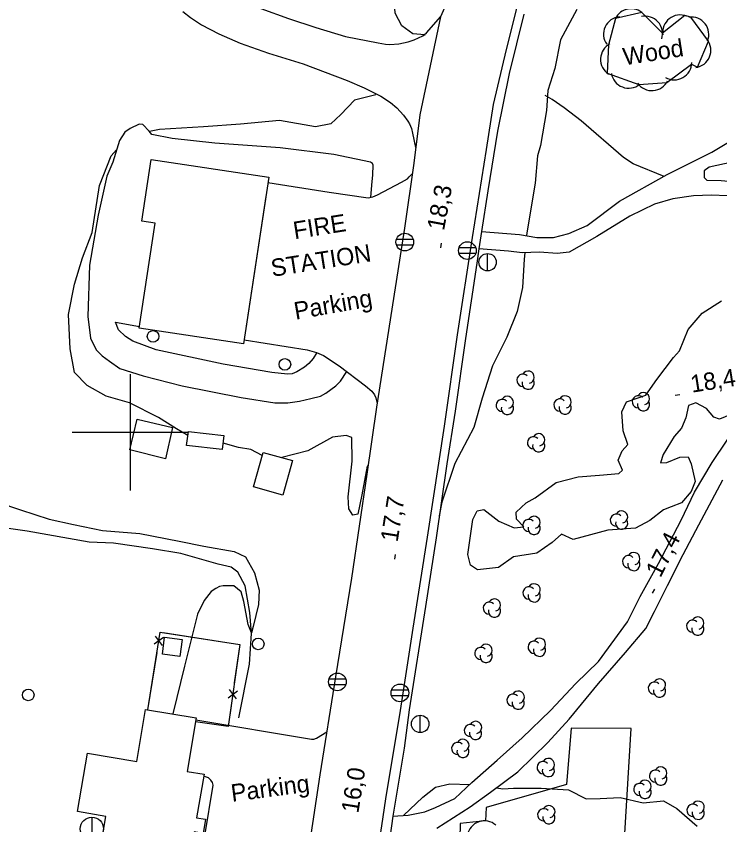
# Model space of a CAD drawing. Extents: x 646142 to 649934, y 5874075 to 5876351.
# Drawn here: x 646580.4 to 646701.5, y 5874932.5 to 5875071.6 of the extents above; entities that cross this region are included whole.
import ezdxf

# ---------------------------------------------------------------- set-up
doc = ezdxf.new("R2010")
doc.units = 0
for name, color, linetype in [('Niveau 19', 7, 'Continuous'), ('Niveau 2', 7, 'Continuous'), ('Niveau 21', 7, 'Continuous'), ('Niveau 22', 7, 'Continuous'), ('Niveau 3', 7, 'Continuous'), ('Niveau 31', 7, 'Continuous'), ('Niveau 34', 7, 'Continuous'), ('Niveau 36', 7, 'Continuous'), ('Niveau 37', 7, 'Continuous'), ('Niveau 4', 7, 'Continuous'), ('Niveau 41', 7, 'Continuous'), ('Niveau 44', 7, 'Continuous'), ('Niveau 52', 7, 'Continuous'), ('Niveau 61', 7, 'Continuous')]:
    doc.layers.add(name, color=color, linetype=linetype)

msp = doc.modelspace()

# ---------------------------------------------------------------- linework, layer by layer
at = {"layer": 'Niveau 19'}
for points in [[(646641.42, 5875040.42), (646641.63, 5875042.53), (646641.77, 5875044.33), (646641.84, 5875045.99), (646641.71, 5875046.26), (646641.4, 5875046.47), (646635.06, 5875047.78), (646625.83, 5875048.97), (646614.56, 5875049.76), (646607.26, 5875050.58), (646603.75, 5875051.27), (646603.26, 5875051.8), (646602.16, 5875052.99), (646601.58, 5875053.02), (646599.98, 5875052.3), (646599.09, 5875051.62), (646598.17, 5875050.21), (646597.92, 5875049.46), (646597.04, 5875046.51), (646595.97, 5875044.1), (646594.51, 5875037.36), (646593.01, 5875028.77), (646592.7, 5875019.93), (646593.19, 5875016.2), (646594.13, 5875014.22), (646595.16, 5875013.17), (646596.43, 5875012.24), (646598.21, 5875010.97), (646602.26, 5875009.71), (646608.94, 5875008), (646619.13, 5875005.99), (646624.89, 5875005.1), (646627.16, 5875005.1), (646629.17, 5875005.36), (646631.11, 5875005.81), (646632.8, 5875006.24), (646633.72, 5875006.72), (646635.43, 5875007.97), (646636.21, 5875008.82), (646637.29, 5875010.45)], [(646632.16, 5875013.71), (646631.49, 5875012.72), (646630.77, 5875011.82), (646630.01, 5875011.21), (646628.69, 5875010.39), (646627.9, 5875010.06), (646627.08, 5875010.02), (646624.39, 5875010.32), (646616.01, 5875011.7), (646604.51, 5875014.2), (646600.48, 5875015.66), (646599.18, 5875016.49), (646597.99, 5875017.62), (646597.51, 5875018.93), (646601.63, 5875018.21)]]:
    msp.add_lwpolyline(points, dxfattribs=at)
at = {"layer": 'Niveau 2'}
for points in [[(646650.73, 5875068.29), (646650.71, 5875068.4), (646648.66, 5875068.54), (646646.8, 5875069.97), (646645.63, 5875072.15), (646645.5, 5875073.77), (646647.46, 5875079.63), (646647.81, 5875081.69), (646646.81, 5875083.25), (646644.56, 5875085.18), (646640.6, 5875087.32), (646634.24, 5875090.51), (646629.79, 5875092.33), (646626.03, 5875093.44), (646624.21, 5875094.41), (646623.63, 5875095.77), (646623.67, 5875097.46), (646626.36, 5875102.85), (646628.98, 5875108.46), (646631.23, 5875113.58), (646634.8, 5875119.82)], [(646676.93, 5875072.77), (646674.11, 5875067.54), (646673.12, 5875062.58), (646671.92, 5875058.82), (646671.69, 5875055.36), (646670.67, 5875049.35), (646670.12, 5875047.56), (646669.76, 5875042.87), (646668.31, 5875034.32), (646668.26, 5875033.82)], [(646642.28, 5875058.07), (646638.62, 5875057.17), (646636.27, 5875054.66), (646634.54, 5875053.07), (646631.91, 5875052.58), (646625.72, 5875053.63), (646619.02, 5875053), (646612.61, 5875052.57), (646605.03, 5875052.11), (646603.31, 5875051.74)], [(646609.95, 5874999.46), (646608, 5875000.59), (646604.87, 5875002.57), (646599.89, 5875005.1), (646595.9, 5875006.2), (646592.61, 5875008.03), (646590.44, 5875010.31), (646589.65, 5875014.34), (646589.39, 5875020.26), (646590.42, 5875025.47), (646591.79, 5875030), (646593.46, 5875034.39), (646594.71, 5875042.47), (646596.73, 5875047.58), (646597.67, 5875048.62)], [(646667.94, 5875030.89), (646667.82, 5875029.79), (646667.58, 5875024.94), (646666.64, 5875020.79), (646664.86, 5875016.35), (646662.36, 5875011.44), (646660.61, 5875005.89), (646659.17, 5875000.83), (646655.9, 5874994.63), (646653.66, 5874988), (646653.22, 5874985.61)], [(646688.81, 5875006.41), (646690.68, 5875009.06), (646693.56, 5875012.89), (646694.57, 5875014.01), (646696.06, 5875017.68), (646698.5, 5875020.48), (646701.81, 5875022.6)], [(646691.83, 5874986.67), (646689.49, 5874984.8), (646686.98, 5874983.5), (646682.25, 5874983.14), (646676.28, 5874981.57), (646674.24, 5874982.46), (646672.67, 5874981.06), (646670.03, 5874979.23), (646666.02, 5874978.57), (646663.44, 5874976.74), (646659.81, 5874976.35), (646658.59, 5874977.12), (646658.14, 5874978.95), (646658.98, 5874985.02), (646659.73, 5874986.47), (646660.87, 5874986.74), (646663.48, 5874984.72), (646666.13, 5874983.59), (646667.8, 5874983.72), (646666.53, 5874985.07), (646666.49, 5874986.24), (646668.21, 5874987.88), (646669.71, 5874988.75), (646673.33, 5874991.36), (646677.14, 5874992.35), (646680.83, 5874992.64), (646684.12, 5874992.89), (646684.77, 5874993.46), (646684.04, 5874995.21), (646684.72, 5874996.84), (646685.68, 5874997.9), (646684.91, 5875000.23), (646684.63, 5875003.53), (646685.48, 5875005.22), (646688.81, 5875006.41)], [(646704.1, 5875003.33), (646701.46, 5875002.25), (646700.5, 5875002.59), (646699.22, 5875004.12), (646697.39, 5875005.09), (646696.15, 5875004.64), (646695.69, 5875002.51), (646694.91, 5875000.7), (646693.64, 5874999.27), (646691.8, 5874996.21), (646691.34, 5874994.72), (646692.38, 5874994.8), (646694.63, 5874995.73), (646696.07, 5874995.79), (646696.58, 5874994.6), (646697.3, 5874991.51), (646696.62, 5874989.83), (646694.93, 5874987.84), (646693.13, 5874987.18), (646691.83, 5874986.67)], [(646640.99, 5874994.22), (646640.83, 5874994.18), (646639.9, 5874989.27), (646639.19, 5874985.9), (646638.33, 5874985.77), (646637.66, 5874986.83), (646637.55, 5874988.92), (646638.21, 5874995.02), (646638.16, 5874999.1), (646637.2, 5874999.43), (646634.84, 5874999.19), (646630.62, 5874996.83), (646626.1, 5874995.65)], [(646622.76, 5874996.02), (646620.77, 5874997.07), (646618.65, 5874997.37), (646615.99, 5874998.12)], [(646577.18, 5874987.99), (646581.1, 5874986.64), (646586.08, 5874985.03), (646590.23, 5874984.12), (646595.27, 5874983.11), (646601.66, 5874982.61), (646608.47, 5874981.26), (646612.67, 5874980.42), (646617.94, 5874979.48), (646619.87, 5874978.58), (646621.44, 5874975.84), (646622.21, 5874972.81), (646622.13, 5874970.35), (646621.21, 5874966.6), (646620.91, 5874965.47), (646620.3, 5874966.91), (646619.57, 5874970.88), (646619.1, 5874972.58)], [(646619.1, 5874972.58), (646619.1, 5874972.58), (646617.88, 5874973.6), (646617.88, 5874973.6), (646616.01, 5874973.61), (646615.37, 5874973.45), (646614.73, 5874973.12), (646613.97, 5874972.61), (646612.74, 5874971.04), (646611.58, 5874968.73), (646609.35, 5874959.78), (646607.34, 5874951.54)], [(646647.04, 5874934.07), (646650.41, 5874937.24), (646652.6, 5874938.92), (646655.06, 5874939.52), (646658.44, 5874939.39)], [(646663.06, 5874938.82), (646664.15, 5874938.65), (646666, 5874938.79), (646670.77, 5874938.75), (646675.45, 5874938.47), (646678.54, 5874936.96), (646680.93, 5874936.97), (646684.34, 5874937.18), (646688.31, 5874936.26), (646691.83, 5874936.59), (646694.15, 5874935.25), (646697.6, 5874932.25)]]:
    msp.add_lwpolyline(points, dxfattribs=at)
at = {"layer": 'Niveau 21'}
for points in [[(646660.51, 5875034.56), (646667.06, 5875034.01), (646670, 5875033.53), (646672.91, 5875033.52), (646675.53, 5875034.19), (646678.66, 5875035.59), (646684.25, 5875039.75), (646692.46, 5875044.34), (646700.16, 5875048.18), (646707.02, 5875052.32), (646714.63, 5875058.49), (646722.48, 5875064.67), (646731.56, 5875071.3), (646740.22, 5875077.43)], [(646666.76, 5875073.84), (646664.76, 5875065.88), (646662.53, 5875056.4), (646661.28, 5875048.67), (646658.88, 5875033.5), (646656.32, 5875016.76), (646654.08, 5875001.03), (646651.13, 5874981.97), (646648.69, 5874966.3), (646646.48, 5874952.16), (646643.99, 5874936.91), (646640, 5874910.28), (646637.43, 5874893.45), (646634.9, 5874876.22), (646631.36, 5874853.87), (646630.32, 5874846.31)], [(646654.14, 5875073.04), (646653.43, 5875071.52), (646649.87, 5875054.63), (646648.82, 5875046.29), (646647.21, 5875035.13), (646642.42, 5875004.35), (646640.75, 5874992.79), (646638.11, 5874974.93), (646635.37, 5874957.92), (646632.67, 5874941.05), (646628.69, 5874914.81), (646625.11, 5874891.13), (646620.83, 5874863.45), (646619.85, 5874857.12), (646619.38, 5874853.76), (646619.06, 5874851.3)], [(646740.49, 5875073.2), (646731.08, 5875066.31), (646725.72, 5875062.41), (646716.46, 5875055.07), (646708.41, 5875048.52), (646705.75, 5875046.92), (646699.71, 5875045.64), (646698.83, 5875044.99), (646698.81, 5875043.83), (646699.31, 5875043.4), (646701.75, 5875043.35), (646704.21, 5875043.08)], [(646702.8, 5875040.67), (646700.12, 5875040.81), (646696.99, 5875040.69), (646693.44, 5875040.19), (646690.26, 5875039.25), (646686.02, 5875037.18), (646680.38, 5875033.72), (646675.61, 5875031.02), (646673.54, 5875030.75), (646670.5, 5875030.98), (646667.49, 5875030.87), (646665.14, 5875031.16), (646660.06, 5875031.58)], [(646645.23, 5874933.93), (646647.89, 5874934.14), (646650.75, 5874934.71), (646652.55, 5874935.43), (646655.92, 5874936.98), (646658.83, 5874939.77), (646663.17, 5874943.6), (646667.51, 5874947.44), (646672.35, 5874952.13), (646676.74, 5874956.78), (646680.61, 5874960.58), (646685.63, 5874967.37), (646687.82, 5874971.74), (646690.95, 5874977.45), (646694.87, 5874984.86), (646697.14, 5874989.7), (646700.2, 5874994.82), (646705.27, 5875002.31)], [(646652.79, 5874931.87), (646658.54, 5874935.58), (646662.06, 5874938.07), (646666.77, 5874941.58), (646671.94, 5874946.65), (646675.56, 5874950.66), (646680.63, 5874956.76), (646685.31, 5874962.14), (646688.8, 5874966.25), (646690.3, 5874969.16), (646692.49, 5874973.64), (646695.19, 5874978.98), (646697.9, 5874984.08), (646702.02, 5874991.85)]]:
    msp.add_lwpolyline(points, dxfattribs=at)
at = {"layer": 'Niveau 22'}
for points in [[(646667.76, 5875071.97), (646665.24, 5875061.76), (646663.27, 5875051.83), (646661.56, 5875041.57), (646660.51, 5875034.56), (646660.06, 5875031.58), (646659.69, 5875029.08), (646657.74, 5875016.12), (646655.98, 5875003.64), (646654.52, 5874994.56), (646652.67, 5874981.84), (646650.85, 5874970.05), (646648.02, 5874952.23), (646647.17, 5874945.63), (646645.23, 5874933.93), (646644.74, 5874930.25), (646644.01, 5874924.74), (646642.84, 5874916.36), (646640.89, 5874904.65), (646639.63, 5874895.9), (646637.92, 5874885.6), (646635.53, 5874870.69), (646633.22, 5874854.95), (646632.26, 5874848.21)], [(646691.93, 5875044.04), (646686.61, 5875046.18), (646684.95, 5875047.26), (646677.68, 5875053.61), (646674.72, 5875055.86), (646672.64, 5875057.24), (646671.45, 5875057.93)]]:
    msp.add_lwpolyline(points, dxfattribs=at)
at = {"layer": 'Niveau 3'}
for p, q in [((646653.47, 5875031.77), (646653.61, 5875032.55)), ((646693.86, 5875006.4), (646694.65, 5875006.52)), ((646645.56, 5874978.18), (646645.69, 5874978.97)), ((646689.94, 5874972.31), (646690.31, 5874973.02))]:
    msp.add_line(p, q, dxfattribs=at)
at = {"layer": 'Niveau 31'}
for points in [[(646623.35, 5875040.56), (646619.51, 5875015.21), (646601.58, 5875017.9), (646604.3, 5875036.01), (646602.02, 5875036.35), (646603.61, 5875046.93), (646623.86, 5875043.89), (646619.51, 5875015.21)], [(646606.1, 5874995.46), (646599.94, 5874996.96), (646601.24, 5875002.28), (646607.31, 5875000.8), (646606.1, 5874995.46)], [(646610.04, 5875000.12), (646616.13, 5874999.48), (646615.87, 5874997.07), (646609.72, 5874997.71), (646610.04, 5875000.12)], [(646627.93, 5874995.14), (646626.29, 5874989.21), (646621.26, 5874990.6), (646622.9, 5874996.53), (646627.93, 5874995.14)], [(646605.55, 5874961.8), (646605.93, 5874964.75), (646608.96, 5874964.35), (646608.58, 5874961.4), (646605.55, 5874961.8)], [(646594.67, 5874927.11), (646595.82, 5874933.92), (646590.95, 5874934.74), (646592.64, 5874944.78), (646601.16, 5874943.34), (646602.67, 5874952.33), (646611.36, 5874950.86), (646609.81, 5874941.65), (646612.72, 5874941.16), (646611.45, 5874933.67), (646613, 5874933.41), (646612.59, 5874930.99), (646611.02, 5874931.25), (646610.5, 5874928.19), (646608.3, 5874928.56), (646607.69, 5874924.92), (646594.67, 5874927.11)]]:
    msp.add_lwpolyline(points, dxfattribs=at)
at = {"layer": 'Niveau 34'}
msp.add_line((646593.41, 5874933.77), (646593.41, 5874929.77), dxfattribs=at)
msp.add_circle((646593.42, 5874931.78), 2, dxfattribs=at)
at = {"layer": 'Niveau 36'}
for p, q in [((646648.73, 5875033.19), (646645.85, 5875033.19)), ((646645.85, 5875032.27), (646648.73, 5875032.27)), ((646659.5, 5875031.72), (646656.62, 5875031.72)), ((646656.62, 5875030.8), (646659.5, 5875030.8)), ((646661.54, 5875027.76), (646661.54, 5875030.76)), ((646637.11, 5874957.52), (646634.23, 5874957.52)), ((646634.23, 5874956.6), (646637.11, 5874956.6)), ((646647.89, 5874955.61), (646645.01, 5874955.61)), ((646645.01, 5874954.69), (646647.89, 5874954.69)), ((646649.95, 5874948.31), (646649.95, 5874951.31))]:
    msp.add_line(p, q, dxfattribs=at)
for centre, radius in [((646647.29, 5875032.73), 1.52), ((646658.06, 5875031.27), 1.52), ((646661.54, 5875029.27), 1.5), ((646603.95, 5875016.51), 1), ((646626.64, 5875011.69), 1), ((646622.06, 5874963.58), 1), ((646635.68, 5874957.06), 1.52), ((646582.47, 5874954.81), 1), ((646646.45, 5874955.16), 1.52), ((646649.94, 5874949.82), 1.5)]:
    msp.add_circle(centre, radius, dxfattribs=at)
at = {"layer": 'Niveau 37'}
for points in [[(646603.04, 5874952.26), (646605.2, 5874965.6), (646618.86, 5874963.5), (646616.89, 5874949.37), (646611.24, 5874950.16)], [(646603.04, 5874952.26), (646605.2, 5874965.6), (646618.86, 5874963.5), (646616.89, 5874949.37), (646611.24, 5874950.16)], [(646603.04, 5874952.26), (646605.2, 5874965.6), (646618.86, 5874963.5), (646616.89, 5874949.37), (646611.24, 5874950.16)], [(646605.68, 5874965.53), (646615.57, 5874964.01)], [(646605.77, 5874964.69), (646604.15, 5874963.52)], [(646605.55, 5874963.3), (646604.37, 5874964.92)], [(646615.57, 5874964.01), (646618.86, 5874963.5), (646617.94, 5874956.9)], [(646603.04, 5874952.26), (646604.64, 5874962.13)], [(646616.87, 5874954.32), (646618.47, 5874955.53)], [(646617.06, 5874955.72), (646618.27, 5874954.12)], [(646617.39, 5874952.94), (646616.89, 5874949.37), (646611.24, 5874950.16)]]:
    msp.add_lwpolyline(points, dxfattribs=at)
at = {"layer": 'Niveau 4'}
msp.add_lwpolyline([(646618.74, 5874950.86), (646620.54, 5874960.1), (646620.92, 5874965.39), (646620.62, 5874968.98), (646619.78, 5874973.59), (646618.54, 5874975.94), (646617.42, 5874976.79), (646615.16, 5874977.32), (646608.72, 5874979.16), (646603.87, 5874979.95), (646597.14, 5874980.95), (646592.94, 5874981.1), (646582.29, 5874982.97), (646578.63, 5874983.5)], dxfattribs=at)
at = {"layer": 'Niveau 41'}
msp.add_lwpolyline([(646648.82, 5874922.16), (646647.61, 5874909.9), (646651.04, 5874909.58), (646650.78, 5874904.8), (646670.34, 5874899.89), (646671.57, 5874903.81), (646680.73, 5874901.67), (646681.68, 5874905.56), (646699.43, 5874902.98), (646700.86, 5874914.1), (646690.39, 5874915.8), (646689.63, 5874930.96), (646685.17, 5874930.97), (646686.24, 5874949.03), (646675.96, 5874949.1), (646675.15, 5874939.41), (646661.32, 5874935.42), (646661.17, 5874933.17), (646656.85, 5874932.71), (646656.75, 5874930.08), (646655.12, 5874928.93), (646656.89, 5874923.29), (646648.82, 5874922.16), (646648.82, 5874922.16)], dxfattribs=at)
at = {"layer": 'Niveau 44'}
msp.add_lwpolyline([(646697.68, 5875062.83), (646699.56, 5875067.31), (646696.51, 5875071.45), (646695.48, 5875071.7), (646691.67, 5875068.69), (646688.11, 5875072.23), (646683.56, 5875071.23), (646682.34, 5875066.67), (646682.12, 5875061.82), (646687.56, 5875059.85), (646692.4, 5875060.22), (646696.67, 5875063.32), (646697.68, 5875062.83)], dxfattribs=at)
for centre, radius, start, end in [((646686.24, 5875069.88), 3, 45.4089, 154.0892), ((646684.5, 5875068.5), 3, 95.1944, 215.1723), ((646688.67, 5875068.6), 3, 342.5825, 102.5604), ((646694.67, 5875068.81), 3, 68.2626, 188.2406), ((646696.63, 5875068.45), 3, 338.2217, 98.1997), ((646683.99, 5875064.17), 3, 117.4542, 237.4322), ((646696.99, 5875065.75), 3, 277.2703, 37.2482), ((646693.69, 5875063.65), 3, 239.6274, 359.6053), ((646685.83, 5875062.22), 3, 188.9555, 308.9334), ((646689.84, 5875061.79), 3, 214.3701, 334.348), ((646667.63, 5875008.96), 1.05, 44.1154, 269.804), ((646668.53, 5875009.49), 1.05, 282.2692, 149.7263), ((646668.53, 5875008.44), 1.05, 166.9369, 29.6212), ((646688.38, 5875005.79), 1.05, 282.2692, 149.7263), ((646664.05, 5875004.63), 1.05, 44.1154, 269.804), ((646664.95, 5875005.16), 1.05, 282.2692, 149.7263), ((646674, 5875004.7), 1.05, 44.1154, 269.804), ((646674.9, 5875005.23), 1.05, 282.2692, 149.7263), ((646687.48, 5875005.26), 1.05, 44.1154, 269.804), ((646664.95, 5875004.11), 1.05, 166.9369, 29.6212), ((646674.9, 5875004.18), 1.05, 166.9369, 29.6212), ((646688.38, 5875004.74), 1.05, 166.9369, 29.6212), ((646669.44, 5874998.19), 1.05, 44.1154, 269.804), ((646670.34, 5874998.72), 1.05, 282.2692, 149.7263), ((646670.34, 5874997.67), 1.05, 166.9369, 29.6212), ((646683.72, 5874984.9), 1.05, 44.1154, 269.804), ((646684.62, 5874985.43), 1.05, 282.2692, 149.7263), ((646668.65, 5874983.98), 1.05, 44.1154, 269.804), ((646669.55, 5874984.51), 1.05, 282.2692, 149.7263), ((646684.62, 5874984.38), 1.05, 166.9369, 29.6212), ((646669.55, 5874983.46), 1.05, 166.9369, 29.6212), ((646686.72, 5874978.28), 1.05, 282.2692, 149.7263), ((646685.82, 5874977.75), 1.05, 44.1154, 269.804), ((646686.72, 5874977.23), 1.05, 166.9369, 29.6212), ((646668.67, 5874972.36), 1.05, 44.1154, 269.804), ((646669.57, 5874972.89), 1.05, 282.2692, 149.7263), ((646669.57, 5874971.84), 1.05, 166.9369, 29.6212), ((646661.83, 5874969.75), 1.05, 44.1154, 269.804), ((646662.73, 5874970.28), 1.05, 282.2692, 149.7263), ((646662.73, 5874969.23), 1.05, 166.9369, 29.6212), ((646697.74, 5874967.18), 1.05, 282.2692, 149.7263), ((646696.84, 5874966.65), 1.05, 44.1154, 269.804), ((646697.74, 5874966.13), 1.05, 166.9369, 29.6212), ((646669.57, 5874963.01), 1.05, 44.1154, 269.804), ((646670.47, 5874963.54), 1.05, 282.2692, 149.7263), ((646660.39, 5874961.96), 1.05, 44.1154, 269.804), ((646661.29, 5874962.49), 1.05, 282.2692, 149.7263), ((646670.47, 5874962.49), 1.05, 166.9369, 29.6212), ((646661.29, 5874961.44), 1.05, 166.9369, 29.6212), ((646690.25, 5874955.99), 1.05, 44.1154, 269.804), ((646691.15, 5874956.52), 1.05, 282.2692, 149.7263), ((646666.82, 5874954.43), 1.05, 282.2692, 149.7263), ((646691.15, 5874955.47), 1.05, 166.9369, 29.6212), ((646665.92, 5874953.9), 1.05, 44.1154, 269.804), ((646666.82, 5874953.38), 1.05, 166.9369, 29.6212), ((646659.48, 5874949.22), 1.05, 282.2692, 149.7263), ((646658.58, 5874948.69), 1.05, 44.1154, 269.804), ((646659.48, 5874948.17), 1.05, 166.9369, 29.6212), ((646657.3, 5874946.14), 1.05, 282.2692, 149.7263), ((646656.4, 5874945.61), 1.05, 44.1154, 269.804), ((646657.3, 5874945.09), 1.05, 166.9369, 29.6212), ((646671.1, 5874942.31), 1.05, 44.1154, 269.804), ((646672, 5874942.84), 1.05, 282.2692, 149.7263), ((646672, 5874941.79), 1.05, 166.9369, 29.6212), ((646690.46, 5874940.85), 1.05, 44.1154, 269.804), ((646691.36, 5874941.38), 1.05, 282.2692, 149.7263), ((646688.66, 5874939.09), 1.05, 282.2692, 149.7263), ((646691.36, 5874940.33), 1.05, 166.9369, 29.6212), ((646687.76, 5874938.56), 1.05, 44.1154, 269.804), ((646688.66, 5874938.04), 1.05, 166.9369, 29.6212), ((646696.91, 5874934.96), 1.05, 44.1154, 269.804), ((646697.81, 5874935.49), 1.05, 282.2692, 149.7263), ((646671.2, 5874934.19), 1.05, 44.1154, 269.804), ((646672.1, 5874934.72), 1.05, 282.2692, 149.7263), ((646697.81, 5874934.44), 1.05, 166.9369, 29.6212), ((646661.01, 5874930.13), 3, 49.3319, 169.3099), ((646672.1, 5874933.67), 1.05, 166.9369, 29.6212)]:
    msp.add_arc(centre, radius, start, end, dxfattribs=at)
at = {"layer": 'Niveau 52'}
for points in [[(646609.05, 5875072.43), (646610.37, 5875071.36), (646612.3, 5875070.14), (646615.3, 5875068.57), (646618.94, 5875066.94), (646623.82, 5875065.24), (646629.78, 5875063.4), (646637.35, 5875060.51), (646640.27, 5875059.29), (646643.16, 5875057.83), (646644.8, 5875056.75), (646645.94, 5875055.81), (646647.09, 5875054.6), (646647.83, 5875053.54), (646648.08, 5875053.06), (646648.43, 5875052.25), (646648.63, 5875051.49), (646649.16, 5875049)], [(646622.51, 5875072.93), (646627.25, 5875071.2), (646631.99, 5875069.63), (646637.07, 5875068.13), (646642.71, 5875066.99), (646643.94, 5875066.79), (646644.72, 5875066.72), (646646.29, 5875066.82), (646647.87, 5875067.18), (646648.9, 5875067.56), (646650.42, 5875068.25), (646651, 5875068.72), (646652.3, 5875070.17), (646653.43, 5875071.52)], [(646623.72, 5875042.99), (646634.26, 5875041.35), (646641, 5875040.33), (646641.76, 5875040.5), (646642.59, 5875040.88), (646646.71, 5875043.07), (646647.77, 5875043.61), (646648.07, 5875043.94), (646648.56, 5875044.46)], [(646619.62, 5875015.9), (646630.5, 5875014.2), (646632.1, 5875013.74), (646633.27, 5875013.23), (646635.98, 5875011.44), (646640.51, 5875008), (646641.63, 5875007.1), (646642.08, 5875006.47), (646642.29, 5875005.91), (646642.51, 5875004.95)], [(646611.31, 5874950.54), (646631.21, 5874947.22), (646631.64, 5874947.22), (646632.06, 5874947.36), (646633.86, 5874948.46)], [(646629.74, 5874921.72), (646612.35, 5874924.53), (646613.17, 5874930.54), (646612.87, 5874930.58), (646614.27, 5874939.27), (646614.17, 5874939.72), (646613.91, 5874940.15), (646613.5, 5874940.52), (646613.17, 5874940.68), (646612.95, 5874940.73), (646612.65, 5874940.77)]]:
    msp.add_lwpolyline(points, dxfattribs=at)
at = {"layer": 'Niveau 61'}
for points in [[(646600, 5875010), (646600, 5875000), (646600, 5874990)], [(646590, 5875000), (646600, 5875000), (646610, 5875000)]]:
    msp.add_lwpolyline(points, dxfattribs=at)

# ---------------------------------------------------------------- texts
at = {"layer": 'Niveau 3'}
for s, rotation, p in [('18,3 ', 79.4381, (646654.03, 5875034.59)), ('18,4 ', 8.9405, (646696.71, 5875006.81)), ('17,7 ', 81.0512, (646646.05, 5874981.02)), ('17,4 ', 62.8779, (646691.29, 5874974.85)), ('16,0 ', 80.8186, (646639.28, 5874934.36))]:
    msp.add_text(s, height=3, rotation=rotation, dxfattribs=at).set_placement(p)
at = {"layer": 'Niveau 31'}
for s, p in [('FIRE', (646628.32, 5875033.22)), ('STATION', (646624.49, 5875026.75))]:
    msp.add_text(s, height=3, rotation=8.941, dxfattribs=at).set_placement(p)
at = {"layer": 'Niveau 44'}
msp.add_text('Wood', height=3, rotation=8.9405, dxfattribs=at).set_placement((646685.1, 5875063.13))
at = {"layer": 'Niveau 52'}
for rotation, p in [(9.9016, (646628.49, 5875019.37)), (7.5056, (646617.56, 5874936.41))]:
    msp.add_text('Parking', height=3, rotation=rotation, dxfattribs=at).set_placement(p)

doc.saveas('drawing.dxf')
